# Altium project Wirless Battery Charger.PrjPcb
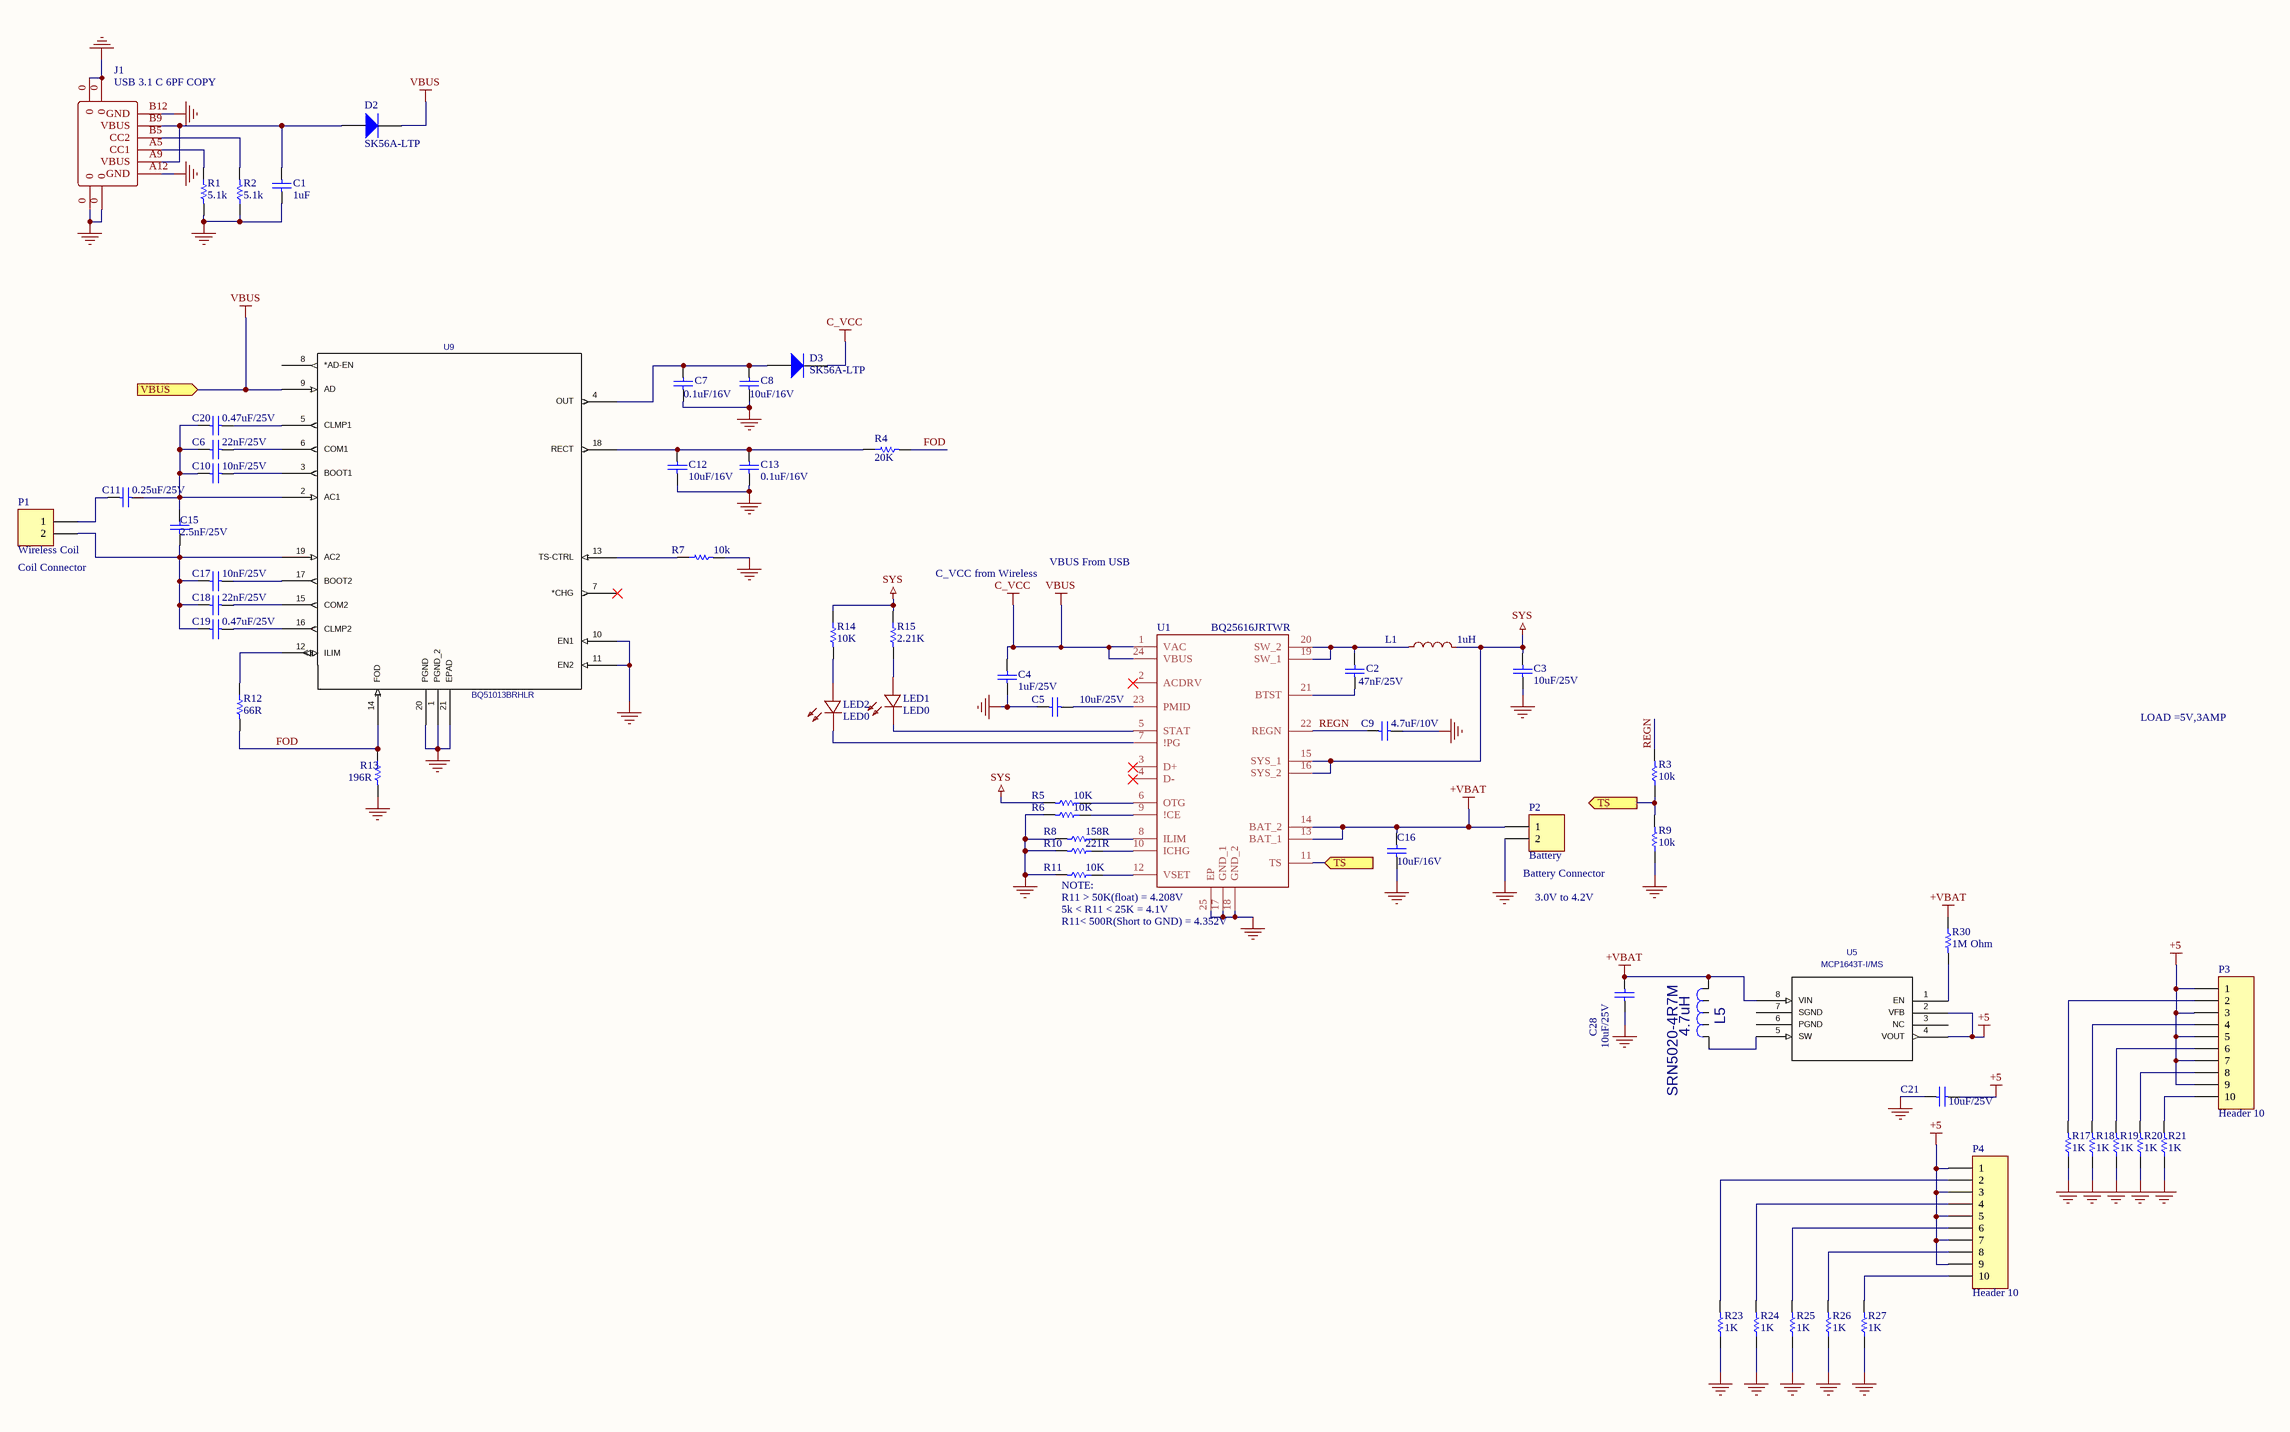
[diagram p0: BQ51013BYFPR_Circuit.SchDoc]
1 sheet, 61 parts. Net scope: flat (ports and power ports of the same name join across sheets).
Board file: PCB_BQ51013BYFPR.PcbDoc

## Sheet BQ51013BYFPR_Circuit.SchDoc
size C

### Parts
C1  value 1uF  [0805-CAP]  (hidden comment: Cap)
C2  value 47nF/25V  [0805-CAP]  (hidden comment: Cap)
C3  value 10uF/25V  [0805-CAP]  (hidden comment: Cap)
C4  value 1uF/25V  [0805-CAP]  (hidden comment: Cap)
C5  value 10uF/25V  [0805-CAP]  (hidden comment: Cap)
C6  value 22nF/25V  [0402-A]  (hidden comment: Cap)
C7  value 0.1uF/16V  [0402-A]  (hidden comment: Cap)
C8  value 10uF/16V  [0805-CAP]  (hidden comment: Cap)
C9  value 4.7uF/10V  [0805-CAP]  (hidden comment: Cap)
C10  value 10nF/25V  [0402-A]  (hidden comment: Cap)
C11  value 0.25uF/25V  [0402-A]  (hidden comment: Cap)
C12  value 10uF/16V  [0805-CAP]  (hidden comment: Cap)
C13  value 0.1uF/16V  [0402-A]  (hidden comment: Cap)
C15  value 2.5nF/25V  [0402-A]  (hidden comment: Cap)
C16  value 10uF/16V  [0805-CAP]  (hidden comment: Cap)
C17  value 10nF/25V  [0402-A]  (hidden comment: Cap)
C18  value 22nF/25V  [0402-A]  (hidden comment: Cap)
C19  value 0.47uF/25V  [0402-A]  (hidden comment: Cap)
C20  value 0.47uF/25V  [0402-A]  (hidden comment: Cap)
C21  value 10uF/25V  [0805-CAP]  (hidden comment: Cap)
C28  value 10uF/25V  [0805-CAP]  (hidden comment: Cap)
D2  SK56A-LTP  [SMC]
D3  SK56A-LTP  [SMC]
J1  USB 3.1 C 6PF COPY  [USB-C-SMD_TYPE-C-USB-13]
L1  1uH  [IND-SMD_L4.1-W3.2]
L5  4.7uH  value SRN5020-4R7M  [IND_BOURNS_SRN50]
LED1  LED0  [1608[0603]_LED]
LED2  LED0  [1608[0603]_LED]
P1  Wireless Coil  [HDR1X2]
P2  Battery  [HDR1X2]
P3  Header 10  [HDR1X10]
P4  Header 10  [HDR1X10]
R1  value 5.1k  [1608[0603]]  (hidden comment: Res1)
R2  value 5.1k  [1608[0603]]  (hidden comment: Res1)
R3  value 10k  [0402-A]  (hidden comment: Res1)
R4  value 20K  [0402-A]  (hidden comment: Res1)
R5  value 10K  [0402-A]  (hidden comment: Res1)
R6  value 10K  [0402-A]  (hidden comment: Res1)
R7  value 10k  [0402-A]  (hidden comment: Res1)
R8  value 158R  [0402-A]  (hidden comment: Res1)
R9  value 10k  [0402-A]  (hidden comment: Res1)
R10  value 221R  [0402-A]  (hidden comment: Res1)
R11  value 10K  [0402-A]  (hidden comment: Res1)
R12  value 66R  [0402-A]  (hidden comment: Res1)
R13  value 196R  [0402-A]  (hidden comment: Res1)
R14  value 10K  [0402-A]  (hidden comment: Res1)
R15  value 2.21K  [0402-A]  (hidden comment: Res1)
R17  value 1K  [0402-A]  (hidden comment: Res1)
R18  value 1K  [0402-A]  (hidden comment: Res1)
R19  value 1K  [0402-A]  (hidden comment: Res1)
R20  value 1K  [0402-A]  (hidden comment: Res1)
R21  value 1K  [0402-A]  (hidden comment: Res1)
R23  value 1K  [0402-A]  (hidden comment: Res1)
R24  value 1K  [0402-A]  (hidden comment: Res1)
R25  value 1K  [0402-A]  (hidden comment: Res1)
R26  value 1K  [0402-A]  (hidden comment: Res1)
R27  value 1K  [0402-A]  (hidden comment: Res1)
R30  value 1M Ohm  [0402-A]  (hidden comment: Res1)
U1  BQ25616JRTWR  [QFN50P400X400X80]
U5  MCP1643T-I/MS  [MSOP8_MC_MCH]
U9  BQ51013BRHLR  [RHL20_2P05X3P05]

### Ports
TS (in), TS (out), VBUS (in)

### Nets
+5: C21.1 P3.1 P3.3 P3.5 P3.7 P3.9 P4.1 P4.3 P4.5 P4.7 P4.9 U5.2(VFB) U5.4(VOUT)
+VBAT: C16.1 C28.2 L5.1 P2.1 R30.1 U1.13(BAT_1) U1.14(BAT_2) U5.8(VIN)
C_VCC: C4.2 D2.2(K) D3.2(K) U1.1(VAC) U1.24(VBUS) U9.9(AD) ; port VBUS  [also labelled VBUS]
GND: C1.2 C3.1 C4.1 C5.2 C7.1 C8.1 C9.1 C12.1 C13.1 C16.2 C21.2 C28.1 J1.0 J1.A12(GND) J1.B12(GND) P2.2 R1.2 R2.1 R6.2 R7.2 R8.2 R9.1 R10.2 R11.2 R13.2 R17.1 R18.1 R19.1 R20.1 R21.1 R23.1 R24.1 R25.1 R26.1 R27.1 U1.17(GND_1) U1.18(GND_2) U1.25(EP) U9.1(PGND_2) U9.10(EN1) U9.11(EN2) U9.20(PGND) U9.21(EPAD)
SYS: C3.2 L1.2 R5.2 R14.1 R15.1 U1.15(SYS_1) U1.16(SYS_2)
FOD: R4.2 R12.2 R13.1 U9.14(FOD)
REGN: C9.2 R3.2 U1.22(REGN)
NetC1_1: C1.1 D2.1(A) J1.A9(VBUS) J1.B9(VBUS)
NetC2_1: C2.1 U1.21(BTST)
NetC2_2: C2.2 L1.1 U1.19(SW_1) U1.20(SW_2)
NetC5_1: C5.1 U1.23(PMID)
NetC6_1: C6.1 C10.1 C11.2 C15.2 C20.1 U9.2(AC1)
NetC6_2: C6.2 U9.6(COM1)
NetC7_2: C7.2 C8.2 D3.1(A) U9.4(OUT)
NetC10_2: C10.2 U9.3(BOOT1)
NetC11_1: C11.1 P1.1
NetC12_2: C12.2 C13.2 R4.1 U9.18(RECT)
NetC15_1: C15.1 C17.1 C18.1 C19.1 P1.2 U9.19(AC2)
NetC17_2: C17.2 U9.17(BOOT2)
NetC18_2: C18.2 U9.15(COM2)
NetC19_2: C19.2 U9.16(CLMP2)
NetC20_2: C20.2 U9.5(CLMP1)
NetJ1_A5: J1.A5(CC1) R1.1
NetJ1_B5: J1.B5(CC2) R2.2
NetL5_2: L5.2 U5.5(SW)
NetLED1_1: LED1.1(A) R15.2
NetLED1_2: LED1.2(K) U1.5(STAT)
NetLED2_1: LED2.1(A) R14.2
NetLED2_2: LED2.2(K) U1.7(!PG)
NetP3_2: P3.2 R17.2
NetP3_4: P3.4 R18.2
NetP3_6: P3.6 R19.2
NetP3_8: P3.8 R20.2
NetP3_10: P3.10 R21.2
NetP4_2: P4.2 R23.2
NetP4_4: P4.4 R24.2
NetP4_6: P4.6 R25.2
NetP4_8: P4.8 R26.2
NetP4_10: P4.10 R27.2
NetR3_1: R3.1 R9.2 U1.11(TS) ; port TS
NetR5_1: R5.1 U1.6(OTG)
NetR6_1: R6.1 U1.9(!CE)
NetR7_1: R7.1 U9.13(TS-CTRL)
NetR8_1: R8.1 U1.8(ILIM)
NetR10_1: R10.1 U1.10(ICHG)
NetR11_1: R11.1 U1.12(VSET)
NetR12_1: R12.1 U9.12(ILIM)
NetR30_2: R30.2 U5.1(EN)

Not connected (* = marked no-connect by the designer): U1 2(ACDRV)* 3(D+)* 4(D-)*; U5 3(NC) 6(PGND) 7(SGND); U9 7(*CHG)* 8(*AD-EN)

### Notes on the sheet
- (near P1) Coil Connector
- C_VCC from Wireless
- VBUS From USB
- LOAD =5V,3AMP
- (near R11) NOTE:
- Battery Connector
- (near U1) R11 > 50K(float) = 4.208V
- 5k < R11 < 25K = 4.1V
- R11< 500R(Short to GND) = 4.352V
- 3.0V to 4.2V

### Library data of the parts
C1-C13 C15-C21 C28 = Cap: Capacitor
D2 D3 = Diode: DIODE SCHOTTKY 5A 60V SMA
L1 = Inductor
L5 = SRN5020-4R7M: Mfr_Name: Bourns Electronics; C: Copyright (C) 2015 Accelerated Designs. All rights reserved
P1 P2 = Header 2: Header, 2-Pin
P3 P4 = Header 10: Header, 10-Pin
R1-R15 R17-R21 R23-R27 R30 = Res1: Resistor
U5 = MCP1643T-I/MS: Mfr_Name: Microchip; C: Copyright (C) 2018 Accelerated Designs. All rights reserved
U9 = BQ51013BRHLR: Mfr_Name: Texas Instruments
